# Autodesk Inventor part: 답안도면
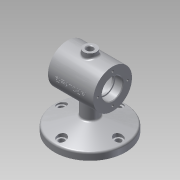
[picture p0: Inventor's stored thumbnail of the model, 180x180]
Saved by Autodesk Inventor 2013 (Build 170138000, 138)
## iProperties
Created: 2018-12
Part Number: 답안도면
Material: 알루미늄 6061
Document SubType Name: Modeling
Designer: Administrator
Density: 2.71 g/cm^3
Mass: 664.779 g
Surface Area: 551.02 cm^2
Volume: 245.306 cm^3
Author: Administrator
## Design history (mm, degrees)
sketch "스케치1"
  geometry: L1 (-35, 0)-(35, 0); L2 (35, 0)-(35, 30); L3 (35, 30)-(-35, 30); L4 (-35, 30)-(-35, 0); L5 (-35, 16)-(-23, 16); L6 (-23, 16)-(-23, 14); L7 (-23, 14)-(-20, 14); L8 (-20, 14)-(-20, 25); L9 (-20, 25)-(20, 25); L10 (20, 25)-(20, 14); L11 (20, 14)-(23, 14); L12 (23, 14)-(23, 16); L13 (23, 16)-(35, 16); 2 further points
  constraints: 26 end point, 6 parallel, 6 perpendicular, 4 collinear, 2 point on line, 1 coincident, 1 horizontal, 1 midpoint
  dimensions: "d0" = 70 distance of L2.end L3.end; "d2" = 60 diameter of L3 L1; "d3" = 28 diameter of L7 L1; "d4" = 50 diameter of L9 L1; "d5" = 32 diameter of L5 L1; "d6" = 12 distance of L5.start L5.end; "d7" = 40 distance of L8.end L9.end
revolve "회전1" sketch "스케치1" stored, may be unused: angle "d8" = 90 deg
sketch "스케치3"
  geometry: L1 (0, -26.988)-(0, -75); L2 (0, -75)-(55, -75); L3 (55, -75)-(55, -64); L4 (55, -64)-(12, -52.478); L5 (12, -52.478)-(12, -25.4); L6 (12, -25.4)-(0, -26.988); 1 further point
  constraints: 12 end point, 2 parallel, 1 perpendicular, 1 vertical, 1 vertical alignment
  dimensions: "d14" = 75 distance from line of L2 point (0, 0); "d15" = 11 distance of L2.end L3.end; "d16" = 75 deg angle of L3 L4; "d17" = 12 distance between parallel lines of L5 L1; "d18" = 55 distance of L1.end L2.end
revolve "회전2" sketch "스케치3" stored, may be unused: angle "d19" = 90 deg
node "작업 평면2"
sketch "스케치4"
  geometry: C1 r 10 at (0, 0); C2 r 5 at (0, 0); 1 further point
  constraints: 2 centre point, 2 coincident
  dimensions: "d21" = 20 diameter of C1; "d23" = 10 diameter of C2
extrude "돌출2" join sketch "스케치4" stored distance "d24" = 10; taper "d25" = 0 deg
feature "면 삭제1"
sketch "스케치5"
  geometry: C1 r 16 at (0, 0) reference; 1 further point
  constraints: 1 horizontal alignment
  dimensions: "d26" = 23 distance of C1.centre point (-23, 0)
hole "구멍1" sketch "스케치5" at (-23, 0) diameter "d27" = 3.242; stored, may be unused: countersink angle "d31" = 90 deg, drill point angle "d33" = 118 deg; dims "d28" = 8, "d29" = 4, "d30" = 2, "d32" = 10
fillet "모깎기1" dims "d37" = 3, "d53" = 0.3
chamfer "모따기1" distance "d38" = 1; stored, may be unused: second distance "d39" = 2, angle "d40" = 45 deg
node "작업 평면3"
sketch "스케치6"
  geometry: 3 further points
  constraints: 1 horizontal alignment
  dimensions: "d42" = 44 distance of point (-44, 0) point (0, 0)
hole "구멍2" sketch "스케치6" at (-44, 0), (-34.925, 88.9) diameter "d43" = 9; stored, may be unused: countersink angle "d47" = 90 deg, drill point angle "d49" = 118 deg; dims "d44" = 9, "d45" = 14, "d46" = 10, "d48" = 10
node "작업 평면4"
sketch "스케치7"
  geometry: L1 (-35, -30)-(-35, 30) reference; 2 further points
  constraints: 1 other
  dimensions: "d54" = 35 distance from line of point (0, 0) L1; "d55" = 30 vertical distance of L1.end point (0, 0)
feature "엠보싱1" sketch "스케치7" dims "d0" = 70, "d2" = 60, "d3" = 28, "d4" = 50, "d5" = 32, "d6" = 12, "d7" = 40, "d17" = 12, "d56" = 0.5, "d57" = 0
node "솔리드1"
pattern_circular "원형 패턴1" dims angle "d35" = 360 deg
mirror "대칭1"
pattern_circular "원형 패턴2" dims angle "d51" = 360 deg
other parameters: "d20" = 37
